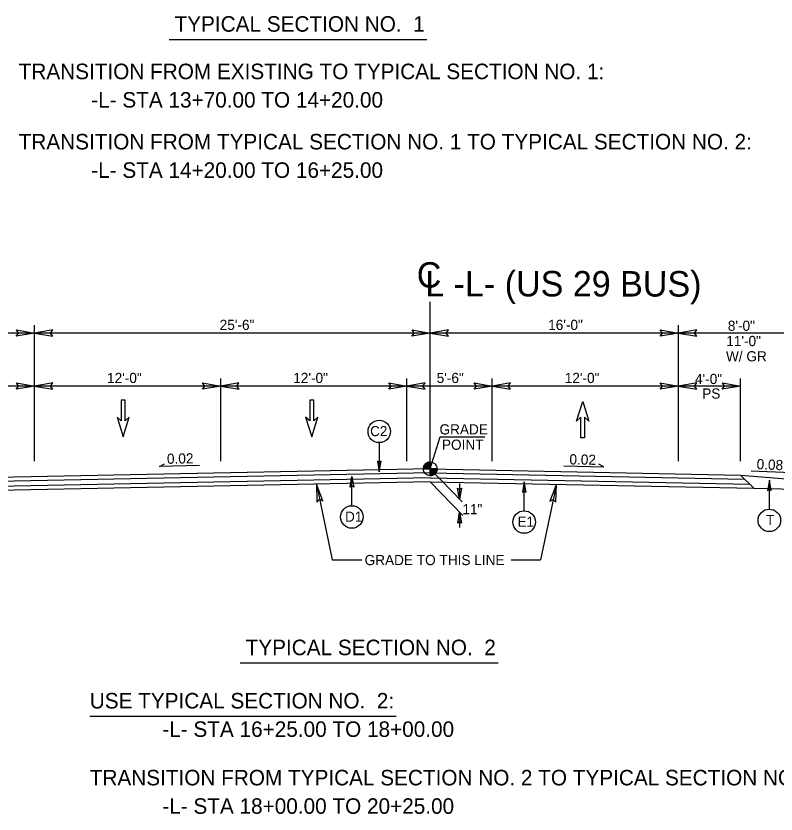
# Model space of a CAD drawing. Extents: x 1901582 to 1902252, y 193723 to 194156.
# Drawn here: x 1902061.9 to 1902110.9, y 194052.7 to 194104.2 of the extents above; entities that cross this region are included whole.
import ezdxf

# ---------------------------------------------------------------- set-up
doc = ezdxf.new("R2010")
doc.units = 0
for name, color, linetype in [('Old_Level_1', 7, 'Continuous'), ('Old_Level_11', 7, 'Continuous'), ('Old_Level_2', 7, 'Continuous'), ('Old_Level_20', 7, 'Continuous'), ('Prop Dimension', 7, 'Continuous'), ('Prop Dimension Text', 7, 'Continuous'), ('Typical Grade Point Symbol CELL', 7, 'Continuous'), ('Typical Pavement Slope Information CELL', 7, 'Continuous'), ('Typical Terminator CELL', 7, 'Continuous'), ('Typical Text Centerline CELL', 7, 'Continuous'), ('Typical Text Grade Point CELL', 7, 'Continuous')]:
    doc.layers.add(name, color=color, linetype=linetype)

# ---------------------------------------------------------------- blocks, each defined once
blk = doc.blocks.new('TERMINATOR')
at = {"layer": 'Typical Terminator CELL'}
blk.add_lwpolyline([(-0.469, 0.081), (0, 0), (-0.471, -0.083), (-0.411, 0)], close=True, dxfattribs=at)

msp = doc.modelspace()

# ---------------------------------------------------------------- linework, layer by layer
at = {"layer": 'Old_Level_1'}
for p, q in [((1902063.086, 194075.483), (1902063.086, 194084.233)), ((1902104.586, 194075.483), (1902104.586, 194084.233)), ((1902063.086, 194083.733), (1902055.086, 194083.733)), ((1902088.519, 194083.733), (1902063.086, 194083.733)), ((1902104.586, 194083.733), (1902088.586, 194083.733)), ((1902112.586, 194083.733), (1902104.586, 194083.733)), ((1902075.086, 194075.483), (1902075.086, 194080.814)), ((1902087.086, 194075.483), (1902087.086, 194080.814)), ((1902092.586, 194075.483), (1902092.586, 194080.814)), ((1902108.586, 194075.483), (1902108.586, 194080.814)), ((1902063.086, 194080.314), (1902059.086, 194080.314)), ((1902075.086, 194080.314), (1902063.086, 194080.314)), ((1902087.086, 194080.314), (1902075.086, 194080.314)), ((1902092.586, 194080.314), (1902087.086, 194080.314)), ((1902104.586, 194080.314), (1902092.586, 194080.314)), ((1902108.586, 194080.314), (1902104.586, 194080.314)), ((1902088.586, 194074.983), (1902059.086, 194074.393)), ((1902088.586, 194074.983), (1902073.586, 194074.683)), ((1902088.586, 194074.983), (1902108.586, 194074.583)), ((1902088.586, 194074.983), (1902090.635, 194072.867)), ((1902088.586, 194074.733), (1902058.831, 194074.138)), ((1902088.586, 194074.733), (1902108.842, 194074.328)), ((1902108.586, 194074.583), (1902109.437, 194073.732)), ((1902108.586, 194074.583), (1902112.586, 194074.263)), ((1902088.586, 194074.149), (1902058.236, 194073.542)), ((1902088.586, 194074.399), (1902058.491, 194073.797)), ((1902081.248, 194074.002), (1902082.271, 194069.111)), ((1902088.586, 194074.399), (1902109.182, 194073.987)), ((1902088.586, 194074.149), (1902109.437, 194073.732)), ((1902088.586, 194074.149), (1902090.693, 194071.973)), ((1902090.477, 194074.029), (1902090.477, 194073.029)), ((1902096.721, 194073.987), (1902095.702, 194069.111)), ((1902109.437, 194073.732), (1902115.167, 194073.618)), ((1902090.477, 194072.196), (1902090.477, 194071.196)), ((1902082.271, 194069.111), (1902084.181, 194069.111)), ((1902093.793, 194069.111), (1902095.702, 194069.111))]:
    msp.add_line(p, q, dxfattribs=at)
at = {"layer": 'Old_Level_11'}
for p, q in [((1902071.75, 194102.654), (1902088.376, 194102.654)), ((1902088.586, 194074.983), (1902088.586, 194085.733)), ((1902085.301, 194076.671), (1902085.301, 194074.797)), ((1902083.531, 194072.606), (1902083.531, 194074.48)), ((1902094.643, 194072.281), (1902094.643, 194074.156)), ((1902110.442, 194072.388), (1902110.442, 194074.263)), ((1902076.332, 194062.483), (1902092.957, 194062.483)), ((1902066.642, 194059.048), (1902086.385, 194059.048))]:
    msp.add_line(p, q, dxfattribs=at)
for points in [[(1902085.186, 194075.469), (1902085.301, 194074.797), (1902085.421, 194075.472), (1902085.301, 194075.386)], [(1902083.416, 194073.809), (1902083.531, 194074.48), (1902083.651, 194073.805), (1902083.531, 194073.891)], [(1902094.759, 194073.484), (1902094.643, 194074.156), (1902094.524, 194073.48), (1902094.643, 194073.566)], [(1902110.558, 194073.591), (1902110.442, 194074.263), (1902110.323, 194073.587), (1902110.442, 194073.673)]]:
    msp.add_lwpolyline(points, close=True, dxfattribs=at)
for centre in [(1902085.301, 194077.396), (1902083.531, 194071.881), (1902110.442, 194071.663), (1902094.643, 194071.556)]:
    msp.add_circle(centre, 0.725, dxfattribs=at)
at = {"layer": 'Prop Dimension'}
for points in [[(1902069.19, 194078.323), (1902068.92, 194078.073), (1902068.92, 194079.407), (1902068.67, 194079.407), (1902068.67, 194078.073), (1902068.399, 194078.323), (1902068.795, 194077.053)], [(1902069.19, 194078.323), (1902068.92, 194078.073), (1902068.92, 194079.407), (1902068.67, 194079.407), (1902068.67, 194078.073), (1902068.399, 194078.323), (1902068.795, 194077.053)], [(1902081.348, 194078.323), (1902081.077, 194078.073), (1902081.077, 194079.407), (1902080.827, 194079.407), (1902080.827, 194078.073), (1902080.556, 194078.323), (1902080.952, 194077.053)], [(1902081.348, 194078.323), (1902081.077, 194078.073), (1902081.077, 194079.407), (1902080.827, 194079.407), (1902080.827, 194078.073), (1902080.556, 194078.323), (1902080.952, 194077.053)], [(1902098.809, 194078.062), (1902098.538, 194078.312), (1902098.538, 194076.978), (1902098.288, 194076.978), (1902098.288, 194078.312), (1902098.017, 194078.062), (1902098.413, 194079.332)], [(1902098.809, 194078.062), (1902098.538, 194078.312), (1902098.538, 194076.978), (1902098.288, 194076.978), (1902098.288, 194078.312), (1902098.017, 194078.062), (1902098.413, 194079.332)]]:
    msp.add_lwpolyline(points, close=True, dxfattribs=at)
at = {"layer": 'Typical Grade Point Symbol CELL'}
for p, q in [((1902088.139, 194074.983), (1902088.586, 194074.983)), ((1902088.586, 194074.983), (1902088.586, 194075.43)), ((1902088.587, 194074.535), (1902088.586, 194074.983)), ((1902089.034, 194074.983), (1902088.586, 194074.983)), ((1902088.586, 194074.983), (1902088.587, 194074.535))]:
    msp.add_line(p, q, dxfattribs=at)
for points in [[(1902088.144, 194075.046), (1902088.144, 194074.983)], [(1902088.153, 194075.092), (1902088.153, 194074.983)], [(1902088.162, 194075.123), (1902088.162, 194074.983)], [(1902088.171, 194075.148), (1902088.171, 194074.983)], [(1902088.18, 194075.169), (1902088.18, 194074.983)], [(1902088.189, 194075.188), (1902088.189, 194074.983)], [(1902088.197, 194075.204), (1902088.197, 194074.983)], [(1902088.206, 194075.218), (1902088.206, 194074.983)], [(1902088.215, 194075.232), (1902088.215, 194074.983)], [(1902088.224, 194075.245), (1902088.224, 194074.983)], [(1902088.233, 194075.257), (1902088.233, 194074.983)], [(1902088.242, 194075.268), (1902088.242, 194074.983)], [(1902088.251, 194075.279), (1902088.251, 194074.983)], [(1902088.26, 194075.289), (1902088.26, 194074.983)], [(1902088.269, 194075.298), (1902088.269, 194074.983)], [(1902088.278, 194075.307), (1902088.278, 194074.983)], [(1902088.287, 194075.315), (1902088.287, 194074.983)], [(1902088.296, 194075.323), (1902088.296, 194074.983)], [(1902088.305, 194075.331), (1902088.305, 194074.983)], [(1902088.314, 194075.338), (1902088.314, 194074.983)], [(1902088.323, 194075.344), (1902088.323, 194074.983)], [(1902088.332, 194075.351), (1902088.332, 194074.983)], [(1902088.341, 194075.357), (1902088.341, 194074.983)], [(1902088.35, 194075.363), (1902088.35, 194074.983)], [(1902088.359, 194075.368), (1902088.359, 194074.983)], [(1902088.368, 194075.373), (1902088.368, 194074.983)], [(1902088.377, 194075.378), (1902088.377, 194074.983)], [(1902088.385, 194075.383), (1902088.385, 194074.983)], [(1902088.394, 194075.387), (1902088.394, 194074.983)], [(1902088.403, 194075.39), (1902088.403, 194074.983)], [(1902088.412, 194075.394), (1902088.412, 194074.983)], [(1902088.421, 194075.398), (1902088.421, 194074.983)], [(1902088.43, 194075.402), (1902088.43, 194074.983)], [(1902088.439, 194075.405), (1902088.439, 194074.983)], [(1902088.448, 194075.408), (1902088.448, 194074.983)], [(1902088.457, 194075.411), (1902088.457, 194074.983)], [(1902088.466, 194075.413), (1902088.466, 194074.983)], [(1902088.475, 194075.416), (1902088.475, 194074.983)], [(1902088.484, 194075.418), (1902088.484, 194074.983)], [(1902088.493, 194075.42), (1902088.493, 194074.983)], [(1902088.502, 194075.422), (1902088.502, 194074.983)], [(1902088.511, 194075.424), (1902088.511, 194074.983)], [(1902088.52, 194075.425), (1902088.52, 194074.983)], [(1902088.529, 194075.426), (1902088.529, 194074.983)], [(1902088.538, 194075.427), (1902088.538, 194074.983)], [(1902088.547, 194075.428), (1902088.547, 194074.983)], [(1902088.556, 194075.429), (1902088.556, 194074.983)], [(1902088.564, 194075.429), (1902088.564, 194074.983)], [(1902088.573, 194075.43), (1902088.573, 194074.983)], [(1902088.582, 194075.43), (1902088.582, 194075.43), (1902088.582, 194074.983)], [(1902088.593, 194074.983), (1902088.593, 194074.535), (1902088.593, 194074.535)], [(1902088.602, 194074.983), (1902088.602, 194074.535)], [(1902088.611, 194074.983), (1902088.611, 194074.536)], [(1902088.62, 194074.983), (1902088.62, 194074.536)], [(1902088.629, 194074.983), (1902088.629, 194074.537)], [(1902088.638, 194074.983), (1902088.638, 194074.538)], [(1902088.647, 194074.983), (1902088.647, 194074.539)], [(1902088.656, 194074.983), (1902088.656, 194074.541)], [(1902088.665, 194074.983), (1902088.665, 194074.542)], [(1902088.674, 194074.983), (1902088.674, 194074.544)], [(1902088.683, 194074.983), (1902088.683, 194074.546)], [(1902088.692, 194074.983), (1902088.692, 194074.548)], [(1902088.701, 194074.983), (1902088.701, 194074.55)], [(1902088.71, 194074.983), (1902088.71, 194074.553)], [(1902088.719, 194074.983), (1902088.719, 194074.555)], [(1902088.728, 194074.983), (1902088.728, 194074.558)], [(1902088.737, 194074.983), (1902088.737, 194074.561)], [(1902088.746, 194074.983), (1902088.746, 194074.564)], [(1902088.754, 194074.983), (1902088.754, 194074.568)], [(1902088.763, 194074.983), (1902088.763, 194074.572)], [(1902088.772, 194074.983), (1902088.772, 194074.576)], [(1902088.781, 194074.983), (1902088.781, 194074.58)], [(1902088.79, 194074.983), (1902088.79, 194074.584)], [(1902088.799, 194074.983), (1902088.799, 194074.589)], [(1902088.808, 194074.983), (1902088.808, 194074.594)], [(1902088.817, 194074.983), (1902088.817, 194074.599)], [(1902088.826, 194074.983), (1902088.826, 194074.605)], [(1902088.835, 194074.983), (1902088.835, 194074.611)], [(1902088.844, 194074.983), (1902088.844, 194074.617)], [(1902088.853, 194074.983), (1902088.853, 194074.623)], [(1902088.862, 194074.983), (1902088.862, 194074.63)], [(1902088.871, 194074.983), (1902088.871, 194074.637)], [(1902088.88, 194074.983), (1902088.88, 194074.645)], [(1902088.889, 194074.983), (1902088.889, 194074.652)], [(1902088.898, 194074.983), (1902088.898, 194074.66)], [(1902088.907, 194074.983), (1902088.907, 194074.669)], [(1902088.916, 194074.983), (1902088.916, 194074.679)], [(1902088.925, 194074.983), (1902088.925, 194074.689)], [(1902088.934, 194074.983), (1902088.934, 194074.7)], [(1902088.942, 194074.983), (1902088.942, 194074.711)], [(1902088.951, 194074.983), (1902088.951, 194074.723)], [(1902088.96, 194074.983), (1902088.96, 194074.736)], [(1902088.969, 194074.983), (1902088.969, 194074.75)], [(1902088.978, 194074.983), (1902088.978, 194074.766)], [(1902088.987, 194074.983), (1902088.987, 194074.783)], [(1902088.996, 194074.983), (1902088.996, 194074.802)], [(1902089.005, 194074.983), (1902089.005, 194074.823)], [(1902089.014, 194074.983), (1902089.014, 194074.849)], [(1902089.023, 194074.983), (1902089.023, 194074.881)], [(1902089.032, 194074.983), (1902089.032, 194074.934)]]:
    msp.add_lwpolyline(points, dxfattribs=at)
msp.add_circle((1902088.587, 194074.983), 0.448, dxfattribs=at)
for start, end in [(90.0095, 180.0095), (270.0095, 0.0095)]:
    msp.add_arc((1902088.587, 194074.983), 0.448, start, end, dxfattribs=at)
at = {"layer": 'Typical Pavement Slope Information CELL'}
for p, q in [((1902071.129, 194075.142), (1902071.461, 194075.31)), ((1902073.716, 194075.205), (1902071.129, 194075.142)), ((1902097.191, 194075.175), (1902099.778, 194075.121)), ((1902099.778, 194075.121), (1902099.445, 194075.288)), ((1902109.281, 194074.864), (1902111.867, 194074.749))]:
    msp.add_line(p, q, dxfattribs=at)
at = {"layer": 'Typical Terminator CELL'}
for points in [[(1902061.915, 194083.935), (1902063.086, 194083.733), (1902061.908, 194083.524), (1902062.058, 194083.733)], [(1902064.258, 194083.935), (1902063.086, 194083.733), (1902064.265, 194083.524), (1902064.115, 194083.733)], [(1902087.415, 194083.935), (1902088.586, 194083.733), (1902087.408, 194083.524), (1902087.558, 194083.733)], [(1902089.758, 194083.935), (1902088.586, 194083.733), (1902089.765, 194083.524), (1902089.615, 194083.733)], [(1902103.415, 194083.935), (1902104.586, 194083.733), (1902103.408, 194083.524), (1902103.558, 194083.733)], [(1902105.758, 194083.935), (1902104.586, 194083.733), (1902105.765, 194083.524), (1902105.615, 194083.733)], [(1902061.915, 194080.516), (1902063.086, 194080.314), (1902061.908, 194080.106), (1902062.058, 194080.314)], [(1902064.258, 194080.516), (1902063.086, 194080.314), (1902064.265, 194080.106), (1902064.115, 194080.314)], [(1902073.915, 194080.516), (1902075.086, 194080.314), (1902073.908, 194080.106), (1902074.058, 194080.314)], [(1902076.258, 194080.516), (1902075.086, 194080.314), (1902076.265, 194080.106), (1902076.115, 194080.314)], [(1902085.915, 194080.516), (1902087.086, 194080.314), (1902085.908, 194080.106), (1902086.058, 194080.314)], [(1902088.258, 194080.516), (1902087.086, 194080.314), (1902088.265, 194080.106), (1902088.115, 194080.314)], [(1902091.415, 194080.516), (1902092.586, 194080.314), (1902091.408, 194080.106), (1902091.558, 194080.314)], [(1902093.758, 194080.516), (1902092.586, 194080.314), (1902093.765, 194080.106), (1902093.615, 194080.314)], [(1902103.415, 194080.516), (1902104.586, 194080.314), (1902103.408, 194080.106), (1902103.558, 194080.314)], [(1902105.758, 194080.516), (1902104.586, 194080.314), (1902105.765, 194080.106), (1902105.615, 194080.314)], [(1902107.415, 194080.516), (1902108.586, 194080.314), (1902107.408, 194080.106), (1902107.558, 194080.314)], [(1902081.674, 194072.927), (1902081.248, 194074.002), (1902081.285, 194072.839), (1902081.453, 194073.023)], [(1902096.68, 194072.831), (1902096.721, 194073.987), (1902096.288, 194072.906), (1902096.517, 194073.007)]]:
    msp.add_lwpolyline(points, close=True, dxfattribs=at)
at = {"layer": 'Typical Text Grade Point CELL'}
for p, q in [((1902088.586, 194074.983), (1902089.229, 194077.043)), ((1902089.229, 194077.043), (1902092.096, 194077.043))]:
    msp.add_line(p, q, dxfattribs=at)

# ---------------------------------------------------------------- block references
at = {"layer": 'Old_Level_1', "xscale": 1.5, "yscale": 1.5}
for p, rotation in [((1902090.477, 194073.029), -90), ((1902090.477, 194072.196), 90)]:
    msp.add_blockref('TERMINATOR', p, dxfattribs=dict(at, rotation=rotation))

# ---------------------------------------------------------------- texts
at = {"layer": 'Old_Level_1'}
for s, p in [('25\'-6"', (1902075.017, 194083.931)), ('16\'-0"', (1902096.187, 194083.931)), ('8\'-0"', (1902107.766, 194083.876)), ('11\'-0"', (1902107.664, 194082.892)), ('W/ GR', (1902107.647, 194081.908)), ('12\'-0"', (1902067.756, 194080.512)), ('12\'-0"', (1902079.756, 194080.512)), ('5\'-6"', (1902089.002, 194080.512)), ('12\'-0"', (1902097.256, 194080.512)), ('4\'-0"', (1902105.651, 194080.446)), ('GRADE TO THIS LINE', (1902084.356, 194068.778))]:
    msp.add_text(s, height=0.656, dxfattribs=at).set_placement(p)
at = {"layer": 'Old_Level_11'}
for s, p in [('TYPICAL SECTION NO.  1', (1902072.106, 194103.148)), ('TRANSITION FROM EXISTING TO TYPICAL SECTION NO. 1: ', (1902062.06, 194100.09)), ('-L- STA 13+70.00 TO 14+20.00', (1902066.736, 194098.259)), ('TRANSITION FROM TYPICAL SECTION NO. 1 TO TYPICAL SECTION NO. 2: ', (1902062.06, 194095.562)), ('-L- STA 14+20.00 TO 16+25.00', (1902066.736, 194093.73)), ('TYPICAL SECTION NO.  2', (1902076.687, 194062.977)), ('USE TYPICAL SECTION NO.  2:', (1902066.642, 194059.542)), ('-L- STA 16+25.00 TO 18+00.00', (1902071.318, 194057.711)), ('TRANSITION FROM TYPICAL SECTION NO. 2 TO TYPICAL SECTION NO. 3: ', (1902066.642, 194054.587)), ('-L- STA 18+00.00 TO 20+25.00', (1902071.318, 194052.755))]:
    msp.add_text(s, height=1, dxfattribs=at).set_placement(p)
at = {"layer": 'Old_Level_2'}
for s, rotation, p in [('0.02', 1.1916, (1902071.622, 194075.302)), ('0.02', 358.8084, (1902097.553, 194075.272)), ('0.08', 357.4644, (1902109.61, 194074.966))]:
    msp.add_text(s, height=0.656, rotation=rotation, dxfattribs=at).set_placement(p)
at = {"layer": 'Old_Level_20'}
for s, height, p in [('C2', 0.6491, (1902084.712, 194077.09)), ('11"', 0.6491, (1902090.663, 194072.059)), ('D1', 0.6491, (1902083.098, 194071.577)), ('E1', 0.6491, (1902094.209, 194071.253)), ('T', 0.649, (1902110.231, 194071.37))]:
    msp.add_text(s, height=height, dxfattribs=at).set_placement(p)
at = {"layer": 'Prop Dimension Text'}
msp.add_text('PS', height=0.656, dxfattribs=at).set_placement((1902106.117, 194079.508))
at = {"layer": 'Typical Text Centerline CELL'}
msp.add_text('C', height=1.64, dxfattribs=at).set_placement((1902087.718, 194086.658))
msp.add_text('L -L- (US 29 BUS)', height=1.64109, rotation=359.9469, dxfattribs=at).set_placement((1902088.264, 194086.098))
at = {"layer": 'Typical Text Grade Point CELL'}
for s, p in [('GRADE', (1902089.183, 194077.199)), ('POINT', (1902089.34, 194076.21))]:
    msp.add_text(s, height=0.656, dxfattribs=at).set_placement(p)

doc.saveas('drawing.dxf')
